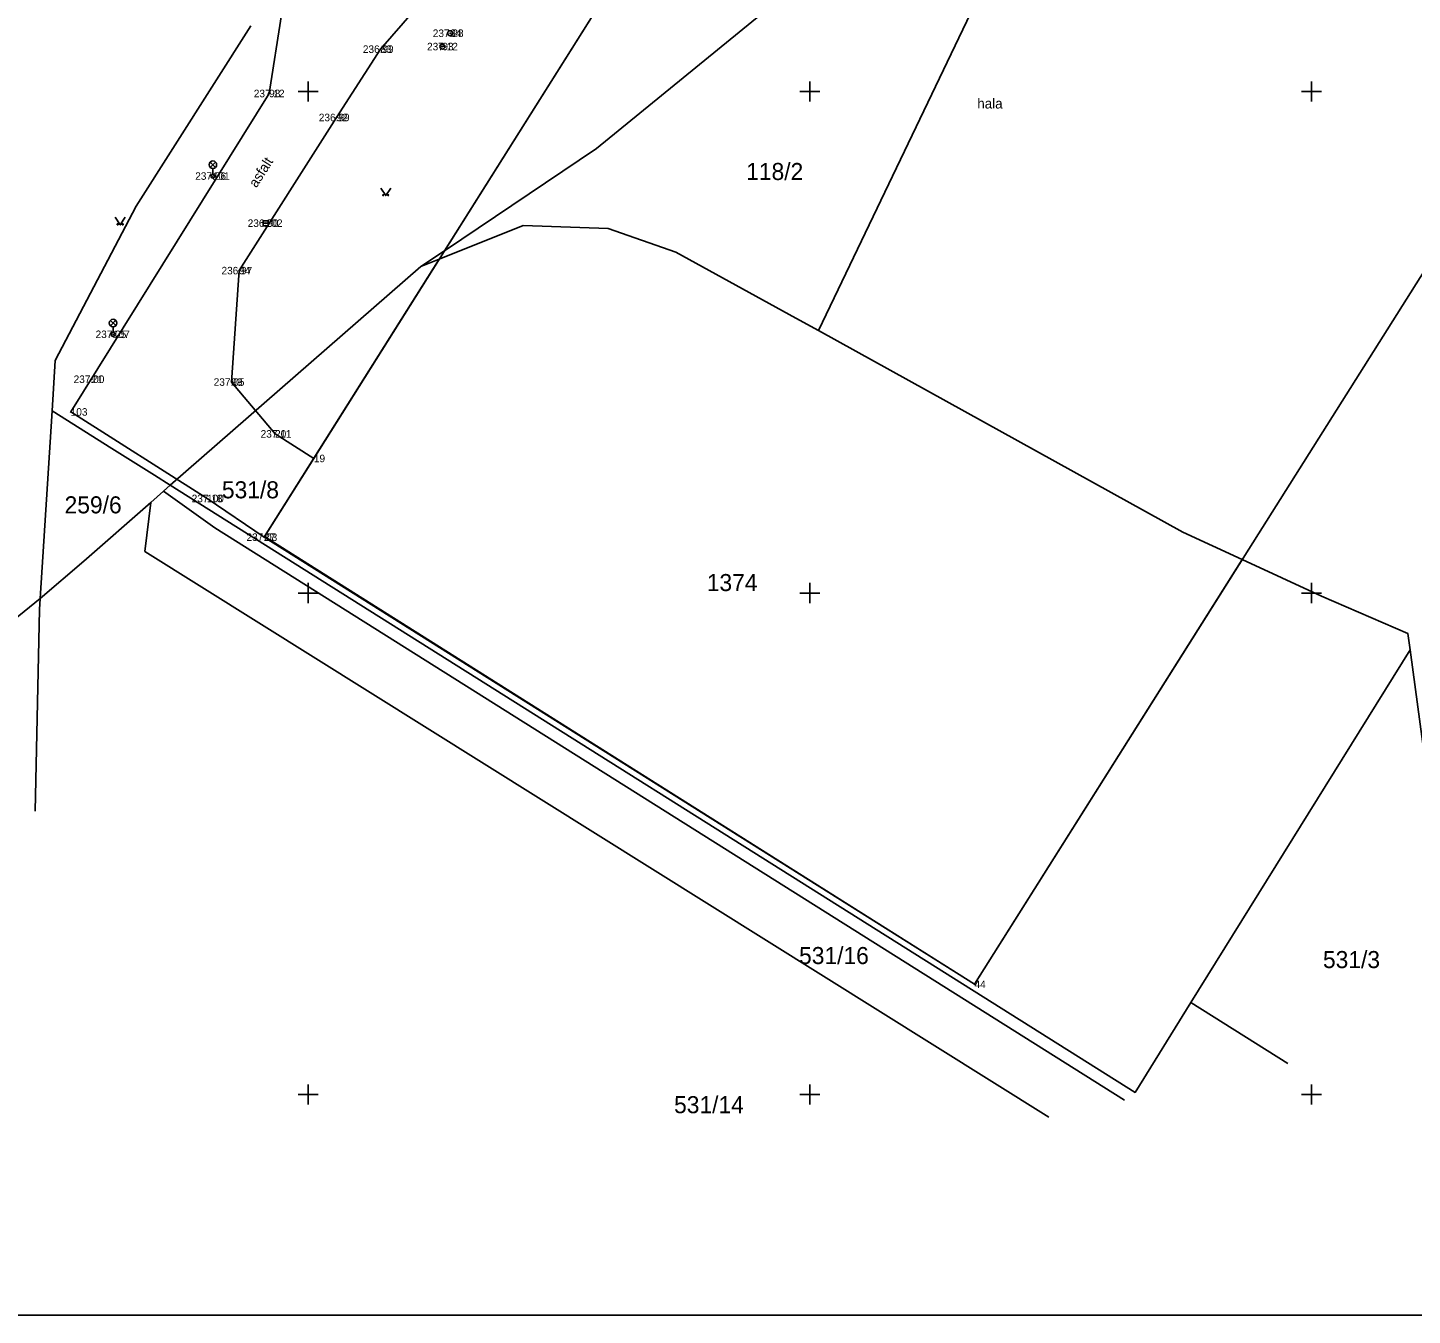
# Model space of a CAD drawing. Extents: x -645398 to -644998, y -1063322 to -1063031.
# Drawn here: x -645278 to -645140, y -1063322 to -1063193.6 of the extents above; entities that cross this region are included whole.
import ezdxf

# ---------------------------------------------------------------- set-up
doc = ezdxf.new("R2010")
doc.units = 0
for name, color, linetype in [('Bod', 7, 'Continuous'), ('Elektrický kabel', 7, 'Continuous'), ('Hranice KN pozemků', 7, 'Continuous'), ('Kanalizace', 7, 'Continuous'), ('Kultury', 7, 'Continuous'), ('Popisy budov', 7, 'Continuous'), ('Popisy povrchů', 7, 'Continuous'), ('Rozhraní ploch', 7, 'Continuous'), ('Rámeček', 7, 'Continuous'), ('Souřadnicové křížky', 7, 'Continuous'), ('Stavby', 7, 'Continuous'), ('Výška', 7, 'Continuous'), ('Čísla parcel', 7, 'Continuous'), ('Čísla stavebních parcel', 7, 'Continuous'), ('Číslo bodu', 7, 'Continuous')]:
    doc.layers.add(name, color=color, linetype=linetype)

msp = doc.modelspace()

# ---------------------------------------------------------------- linework, layer by layer
at = {"layer": 'Bod'}
for p, q in [((-645235.85, -1063194.19), (-645235.9, -1063194.14)), ((-645235.85, -1063194.19), (-645235.9, -1063194.24)), ((-645235.85, -1063194.19), (-645235.8, -1063194.14)), ((-645235.85, -1063194.19), (-645235.8, -1063194.24)), ((-645236.63, -1063195.51), (-645236.68, -1063195.46)), ((-645236.63, -1063195.51), (-645236.68, -1063195.56)), ((-645236.63, -1063195.51), (-645236.58, -1063195.46)), ((-645236.63, -1063195.51), (-645236.58, -1063195.56)), ((-645242.79, -1063195.77), (-645242.84, -1063195.72)), ((-645242.79, -1063195.77), (-645242.84, -1063195.82)), ((-645242.79, -1063195.77), (-645242.74, -1063195.72)), ((-645242.79, -1063195.77), (-645242.74, -1063195.82)), ((-645253.9, -1063200.2), (-645253.95, -1063200.15)), ((-645253.9, -1063200.2), (-645253.95, -1063200.25)), ((-645253.9, -1063200.2), (-645253.85, -1063200.15)), ((-645253.9, -1063200.2), (-645253.85, -1063200.25)), ((-645247.18, -1063202.58), (-645247.23, -1063202.53)), ((-645247.18, -1063202.58), (-645247.13, -1063202.53)), ((-645247.18, -1063202.58), (-645247.23, -1063202.63)), ((-645247.18, -1063202.58), (-645247.13, -1063202.63)), ((-645259.51, -1063208.43), (-645259.56, -1063208.38)), ((-645259.51, -1063208.43), (-645259.56, -1063208.48)), ((-645259.51, -1063208.43), (-645259.46, -1063208.38)), ((-645259.51, -1063208.43), (-645259.46, -1063208.48)), ((-645254.24, -1063213.13), (-645254.29, -1063213.08)), ((-645254.24, -1063213.13), (-645254.29, -1063213.18)), ((-645254.24, -1063213.13), (-645254.19, -1063213.08)), ((-645254.24, -1063213.13), (-645254.19, -1063213.18)), ((-645256.88, -1063217.85), (-645256.93, -1063217.8)), ((-645256.88, -1063217.85), (-645256.93, -1063217.9)), ((-645256.88, -1063217.85), (-645256.83, -1063217.8)), ((-645256.88, -1063217.85), (-645256.83, -1063217.9)), ((-645269.46, -1063224.21), (-645269.51, -1063224.16)), ((-645269.46, -1063224.21), (-645269.51, -1063224.26)), ((-645269.46, -1063224.21), (-645269.41, -1063224.16)), ((-645269.46, -1063224.21), (-645269.41, -1063224.26)), ((-645271.58, -1063228.69), (-645271.63, -1063228.64)), ((-645271.58, -1063228.69), (-645271.63, -1063228.74)), ((-645271.58, -1063228.69), (-645271.53, -1063228.64)), ((-645271.58, -1063228.69), (-645271.53, -1063228.74)), ((-645257.66, -1063228.97), (-645257.71, -1063228.92)), ((-645257.66, -1063228.97), (-645257.71, -1063229.02)), ((-645257.66, -1063228.97), (-645257.61, -1063228.92)), ((-645257.66, -1063228.97), (-645257.61, -1063229.02)), ((-645273.68, -1063231.95), (-645273.73, -1063231.9)), ((-645273.68, -1063231.95), (-645273.73, -1063232)), ((-645273.68, -1063231.95), (-645273.63, -1063231.9)), ((-645273.68, -1063231.95), (-645273.63, -1063232)), ((-645253.31, -1063234.14), (-645253.36, -1063234.09)), ((-645253.31, -1063234.14), (-645253.36, -1063234.19)), ((-645253.31, -1063234.14), (-645253.26, -1063234.09)), ((-645253.31, -1063234.14), (-645253.26, -1063234.19)), ((-645249.44, -1063236.58), (-645249.49, -1063236.53)), ((-645249.44, -1063236.58), (-645249.49, -1063236.63)), ((-645249.44, -1063236.58), (-645249.39, -1063236.53)), ((-645249.44, -1063236.58), (-645249.39, -1063236.63)), ((-645260.09, -1063240.57), (-645260.14, -1063240.52)), ((-645260.09, -1063240.57), (-645260.14, -1063240.62)), ((-645260.09, -1063240.57), (-645260.04, -1063240.52)), ((-645260.09, -1063240.57), (-645260.04, -1063240.62)), ((-645254.39, -1063244.44), (-645254.44, -1063244.39)), ((-645254.39, -1063244.44), (-645254.44, -1063244.49)), ((-645254.39, -1063244.44), (-645254.34, -1063244.39)), ((-645254.39, -1063244.44), (-645254.34, -1063244.49)), ((-645183.59, -1063289.01), (-645183.64, -1063288.96)), ((-645183.59, -1063289.01), (-645183.64, -1063289.06)), ((-645183.59, -1063289.01), (-645183.54, -1063288.96)), ((-645183.59, -1063289.01), (-645183.54, -1063289.06))]:
    msp.add_line(p, q, dxfattribs=at)
at = {"layer": 'Elektrický kabel'}
for p, q in [((-645259.77, -1063207.57), (-645259.25, -1063207.04)), ((-645259.24, -1063207.56), (-645259.77, -1063207.04)), ((-645259.51, -1063208.23), (-645259.51, -1063207.68)), ((-645269.72, -1063223.35), (-645269.2, -1063222.82)), ((-645269.19, -1063223.34), (-645269.72, -1063222.82)), ((-645269.46, -1063224.01), (-645269.46, -1063223.46))]:
    msp.add_line(p, q, dxfattribs=at)
for centre, radius in [((-645235.85, -1063194.19), 0.25), ((-645236.63, -1063195.51), 0.25), ((-645259.51, -1063207.3), 0.375), ((-645259.51, -1063208.43), 0.2), ((-645269.46, -1063223.08), 0.375), ((-645269.46, -1063224.21), 0.2)]:
    msp.add_circle(centre, radius, dxfattribs=at)
at = {"layer": 'Hranice KN pozemků'}
for p, q in [((-645177.04, -1063121.61), (-645236.42, -1063215.87)), ((-645170.69, -1063164.36), (-645221.27, -1063205.67)), ((-645170.69, -1063164.36), (-645199.14, -1063223.84)), ((-645221.27, -1063205.67), (-645236.42, -1063215.87)), ((-645236.96, -1063216.72), (-645228.59, -1063213.36)), ((-645236.42, -1063215.87), (-645238.79, -1063217.46)), ((-645238.79, -1063217.46), (-645263.76, -1063239.26)), ((-645236.96, -1063216.72), (-645254.37, -1063244.36)), ((-645238.79, -1063217.46), (-645236.96, -1063216.72)), ((-645199.14, -1063223.84), (-645162.84, -1063243.95)), ((-645276.71, -1063250.55), (-645275.52, -1063231.85)), ((-645264.44, -1063239.84), (-645263.76, -1063239.26)), ((-645265.68, -1063240.98), (-645264.44, -1063239.84)), ((-645162.84, -1063243.95), (-645156.91, -1063246.67)), ((-645140.17, -1063255.68), (-645162.02, -1063290.83)), ((-645136.03, -1063286.56), (-645140.17, -1063255.68)), ((-645162.02, -1063290.83), (-645152.36, -1063296.91))]:
    msp.add_line(p, q, dxfattribs=at)
for points in [[(-645275.52, -1063231.85), (-645275.24, -1063226.82), (-645267.15, -1063211.42), (-645255.71, -1063193.46)], [(-645228.59, -1063213.36), (-645220.1, -1063213.64), (-645213.37, -1063216.01)], [(-645213.37, -1063216.01), (-645201.39, -1063222.59), (-645199.14, -1063223.84)], [(-645263.76, -1063239.26), (-645265.34, -1063238.26), (-645269.57, -1063235.59), (-645275.52, -1063231.85)], [(-645162.02, -1063290.83), (-645167.59, -1063299.79), (-645263.76, -1063239.26)], [(-645276.71, -1063250.55), (-645272.37, -1063246.83), (-645265.68, -1063240.98)], [(-645176.19, -1063302.27), (-645266.29, -1063245.85), (-645265.68, -1063240.98)], [(-645264.44, -1063239.84), (-645259.31, -1063243.5), (-645168.64, -1063300.57)], [(-645254.37, -1063244.36), (-645183.59, -1063289.01), (-645156.91, -1063246.67)], [(-645156.91, -1063246.67), (-645149.02, -1063250.3), (-645140.39, -1063254.05), (-645140.17, -1063255.68)], [(-645292.7, -1063254.09), (-645286.48, -1063258.46), (-645276.71, -1063250.55)], [(-645276.71, -1063250.55), (-645276.78, -1063251.66), (-645277.21, -1063271.77)]]:
    msp.add_lwpolyline(points, dxfattribs=at)
at = {"layer": 'Kanalizace'}
msp.add_line((-645254.49, -1063213.13), (-645253.99, -1063213.13), dxfattribs=at)
msp.add_lwpolyline([(-645254.49, -1063213.38), (-645253.99, -1063213.38), (-645253.99, -1063212.88), (-645254.49, -1063212.88)], close=True, dxfattribs=at)
at = {"layer": 'Kultury'}
for points in [[(-645242.78, -1063209.63), (-645242.28, -1063210.38), (-645241.78, -1063209.63)], [(-645269.25, -1063212.54), (-645268.75, -1063213.29), (-645268.25, -1063212.54)]]:
    msp.add_lwpolyline(points, dxfattribs=at)
for centre in [(-645242.53, -1063210.33), (-645242.03, -1063210.33), (-645269, -1063213.24), (-645268.5, -1063213.24)]:
    msp.add_circle(centre, 0.05, dxfattribs=at)
at = {"layer": 'Rozhraní ploch'}
for points in [[(-645254.39, -1063244.44), (-645260.09, -1063240.57), (-645273.68, -1063231.95), (-645253.9, -1063200.2), (-645252.67, -1063192.34), (-645253.79, -1063190.64), (-645257.46, -1063187.47), (-645280.34, -1063174.63), (-645291.34, -1063167.5), (-645316.22, -1063151.47), (-645336.53, -1063139.24)], [(-645249.44, -1063236.58), (-645253.31, -1063234.14), (-645257.66, -1063228.97), (-645256.88, -1063217.85), (-645247.18, -1063202.58), (-645242.79, -1063195.77), (-645237.15, -1063189.25), (-645232.94, -1063185.52), (-645227.12, -1063182.6), (-645218.23, -1063181.8), (-645215.89, -1063183.28)]]:
    msp.add_lwpolyline(points, dxfattribs=at)
at = {"layer": 'Rámeček'}
msp.add_line((-645398.25, -1063322.02), (-644998.25, -1063322.02), dxfattribs=at)
at = {"layer": 'Souřadnicové křížky'}
for p, q in [((-645250, -1063199), (-645250, -1063201)), ((-645200, -1063199), (-645200, -1063201)), ((-645150, -1063199), (-645150, -1063201)), ((-645249, -1063200), (-645251, -1063200)), ((-645199, -1063200), (-645201, -1063200)), ((-645149, -1063200), (-645151, -1063200)), ((-645250, -1063249), (-645250, -1063251)), ((-645200, -1063249), (-645200, -1063251)), ((-645150, -1063249), (-645150, -1063251)), ((-645249, -1063250), (-645251, -1063250)), ((-645199, -1063250), (-645201, -1063250)), ((-645149, -1063250), (-645151, -1063250)), ((-645250, -1063299), (-645250, -1063301)), ((-645200, -1063299), (-645200, -1063301)), ((-645150, -1063299), (-645150, -1063301)), ((-645249, -1063300), (-645251, -1063300)), ((-645199, -1063300), (-645201, -1063300)), ((-645149, -1063300), (-645151, -1063300))]:
    msp.add_line(p, q, dxfattribs=at)
at = {"layer": 'Stavby'}
for p, q in [((-645183.59, -1063289.01), (-645106.24, -1063166.23)), ((-645215.89, -1063183.28), (-645249.44, -1063236.58)), ((-645249.44, -1063236.58), (-645254.39, -1063244.44)), ((-645254.39, -1063244.44), (-645183.59, -1063289.01))]:
    msp.add_line(p, q, dxfattribs=at)

# ---------------------------------------------------------------- texts
at = {"layer": 'Popisy budov'}
msp.add_text('hala', height=1, dxfattribs=at).set_placement((-645183.32, -1063201.69))
at = {"layer": 'Popisy povrchů'}
msp.add_text('asfalt', height=1, rotation=57.575, dxfattribs=at).set_placement((-645255.17, -1063209.66))
at = {"layer": 'Výška'}
for s, p in [('237.28', (-645237.59, -1063194.56)), ('236.99', (-645244.56, -1063196.15)), ('237.12', (-645238.16, -1063195.89)), ('237.12', (-645255.43, -1063200.57)), ('236.99', (-645248.95, -1063202.96)), ('237.26', (-645261.27, -1063208.8)), ('236.90', (-645256.04, -1063213.5)), ('236.97', (-645258.65, -1063218.23)), ('237.25', (-645271.2, -1063224.58)), ('237.00', (-645273.39, -1063229.06)), ('237.05', (-645259.43, -1063229.34)), ('237.11', (-645254.75, -1063234.51)), ('237.18', (-645261.62, -1063240.95)), ('237.03', (-645256.16, -1063244.81))]:
    msp.add_text(s, height=0.75, dxfattribs=at).set_placement(p)
at = {"layer": 'Čísla parcel'}
for s, p in [('531/8', (-645258.61, -1063240.56)), ('259/6', (-645274.29, -1063242.06)), ('531/16', (-645201.08, -1063287)), ('531/3', (-645148.86, -1063287.4)), ('531/14', (-645213.54, -1063301.87))]:
    msp.add_text(s, height=1.7, dxfattribs=at).set_placement(p)
at = {"layer": 'Čísla stavebních parcel'}
for s, p in [('118/2', (-645206.35, -1063208.82)), ('1374', (-645210.28, -1063249.81))]:
    msp.add_text(s, height=1.7, dxfattribs=at).set_placement(p)
at = {"layer": 'Číslo bodu'}
for s, p in [('84', (-645235.85, -1063194.56)), ('83', (-645242.79, -1063196.15)), ('93', (-645236.63, -1063195.89)), ('98', (-645253.9, -1063200.57)), ('92', (-645247.18, -1063202.96)), ('101', (-645259.51, -1063208.8)), ('102', (-645254.24, -1063213.5)), ('94', (-645256.88, -1063218.23)), ('107', (-645269.46, -1063224.58)), ('21', (-645271.58, -1063229.06)), ('99', (-645257.66, -1063229.34)), ('103', (-645273.68, -1063232.32)), ('20', (-645253.31, -1063234.51)), ('19', (-645249.44, -1063236.96)), ('100', (-645260.09, -1063240.95)), ('27', (-645254.39, -1063244.81)), ('44', (-645183.59, -1063289.39))]:
    msp.add_text(s, height=0.75, dxfattribs=at).set_placement(p)

doc.saveas('drawing.dxf')
